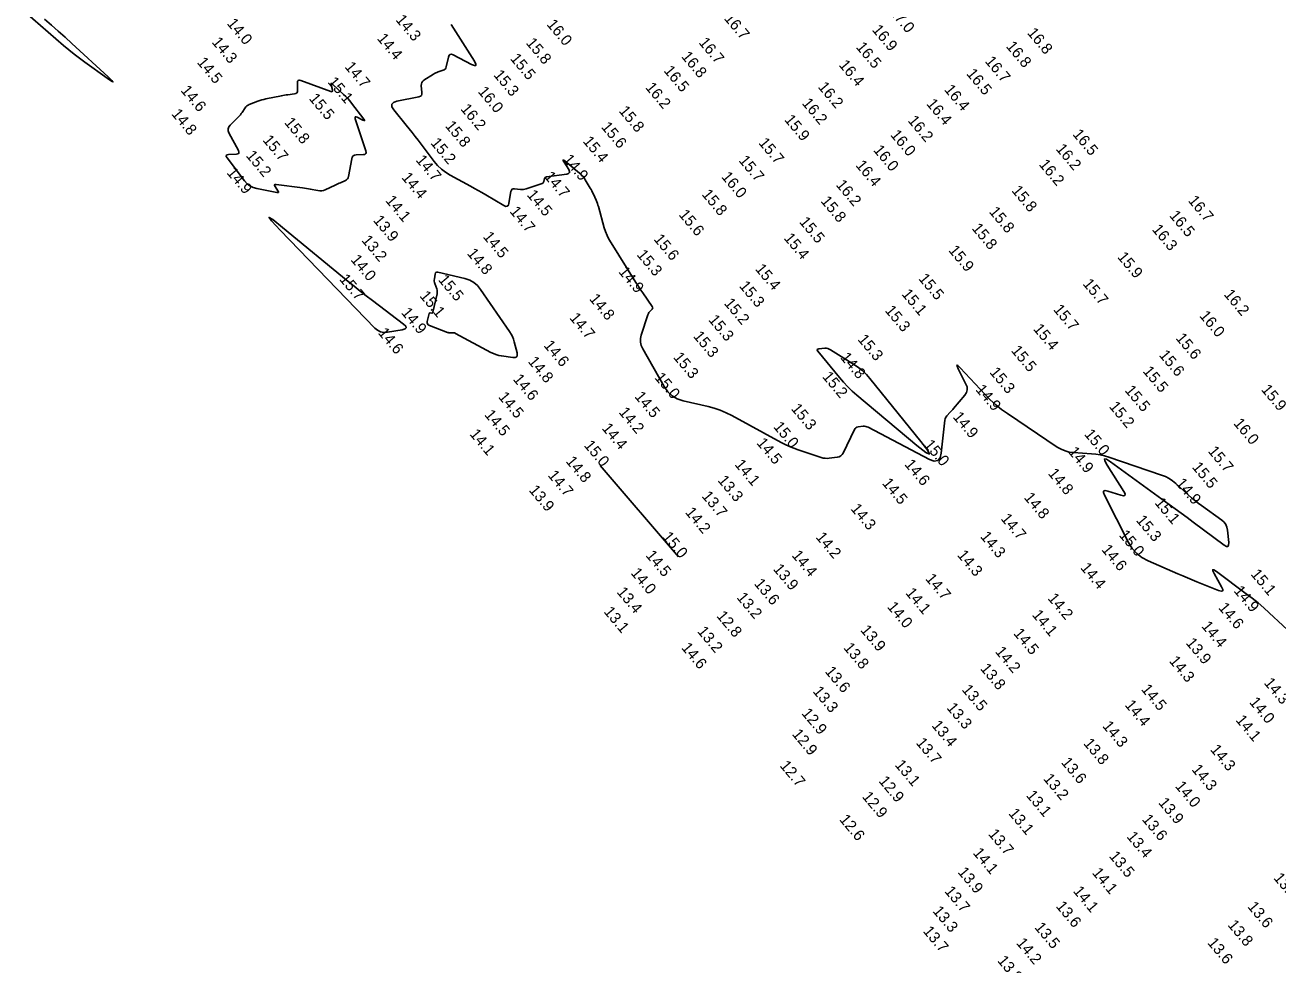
# Model space of a CAD drawing. Extents: x 988130 to 1132882, y 654656 to 841453.
# Drawn here: x 1108628 to 1109193, y 682335 to 682759 of the extents above; entities that cross this region are included whole.
import ezdxf

# ---------------------------------------------------------------- set-up
doc = ezdxf.new("R2010")
doc.units = 0
doc.layers.add('V-TOPO-MAJR', color=7, linetype='Continuous')
doc.layers.add('V-TOPO-SOUN', color=7, linetype='Continuous')

msp = doc.modelspace()

# ---------------------------------------------------------------- linework, layer by layer
at = {"layer": 'V-TOPO-MAJR'}
for points in [[(1108636.86, 682761.26), (1108639.95, 682758.56), (1108643.01, 682755.85), (1108646.06, 682753.11), (1108649.08, 682750.35), (1108665.52, 682735.22), (1108667.2, 682733.62), (1108667.67, 682732.99), (1108666.96, 682733.33), (1108665.05, 682734.64), (1108655.04, 682741.83), (1108652.56, 682743.66), (1108650.12, 682745.54), (1108647.72, 682747.47), (1108645.37, 682749.45), (1108628.06, 682764.38)], [(1109207.17, 682476.66), (1109188.74, 682493.75), (1109186.24, 682496.01), (1109183.68, 682498.2), (1109181.06, 682500.32), (1109178.38, 682502.36), (1109164.89, 682512.38), (1109163.79, 682513.09), (1109163.25, 682513.17), (1109163.27, 682512.63), (1109163.85, 682511.45), (1109167.26, 682505.51), (1109167.8, 682504.29), (1109167.74, 682503.61), (1109167.07, 682503.45), (1109165.79, 682503.83), (1109156.11, 682507.76), (1109153.98, 682508.64), (1109151.84, 682509.53), (1109149.71, 682510.43), (1109147.59, 682511.34), (1109134.13, 682517.14), (1109131.37, 682518.62), (1109128.98, 682520.48), (1109126.96, 682522.75), (1109125.31, 682525.41), (1109114.42, 682546.76), (1109113.99, 682547.91), (1109114.1, 682548.6), (1109114.76, 682548.82), (1109115.97, 682548.58), (1109121.88, 682546.69), (1109123.07, 682546.45), (1109123.69, 682546.64), (1109123.72, 682547.29), (1109123.18, 682548.38), (1109115.65, 682560.32), (1109114.59, 682562.24), (1109114.51, 682563.12), (1109115.38, 682562.98), (1109117.23, 682561.8), (1109143.61, 682542.62), (1109146.33, 682540.63), (1109149.05, 682538.64), (1109151.76, 682536.64), (1109154.47, 682534.63), (1109168.44, 682524.26), (1109169.42, 682523.69), (1109170.08, 682523.69), (1109170.42, 682524.26), (1109170.44, 682525.39), (1109169.89, 682531.03), (1109169.62, 682532.37), (1109169.11, 682533.56), (1109168.33, 682534.6), (1109167.31, 682535.5), (1109158.14, 682542.04), (1109156.61, 682543.17), (1109155.11, 682544.35), (1109153.65, 682545.57), (1109152.23, 682546.84), (1109146.61, 682551.99), (1109145.16, 682553.2), (1109143.6, 682554.23), (1109141.95, 682555.1), (1109140.19, 682555.8), (1109116.39, 682563.89), (1109114.47, 682564.47), (1109112.53, 682564.92), (1109110.56, 682565.24), (1109108.56, 682565.44), (1109100.53, 682565.95), (1109098.57, 682566.2), (1109096.68, 682566.7), (1109094.89, 682567.45), (1109093.17, 682568.45), (1109070.77, 682583.49), (1109068.06, 682585.43), (1109065.47, 682587.51), (1109063, 682589.74), (1109060.66, 682592.11), (1109049.39, 682604.2), (1109048.43, 682605.14), (1109047.98, 682605.36), (1109048.03, 682604.86), (1109048.58, 682603.64), (1109052.06, 682596.85), (1109052.53, 682595.54), (1109052.6, 682594.27), (1109052.25, 682593.05), (1109051.5, 682591.87), (1109046.44, 682585.81), (1109046.08, 682585.38), (1109045.72, 682584.96), (1109045.34, 682584.55), (1109044.96, 682584.14), (1109043.43, 682582.51), (1109043.09, 682582.08), (1109042.83, 682581.62), (1109042.65, 682581.12), (1109042.55, 682580.58), (1109040.93, 682565.73), (1109040.38, 682563.56), (1109039.31, 682562.36), (1109037.72, 682562.14), (1109035.61, 682562.89), (1109007.94, 682577.39), (1109007.42, 682577.62), (1109006.88, 682577.76), (1109006.32, 682577.82), (1109005.75, 682577.8), (1109003.42, 682577.53), (1109002.88, 682577.4), (1109002.42, 682577.16), (1109002.05, 682576.81), (1109001.75, 682576.34), (1108996.67, 682565.75), (1108996.2, 682565.01), (1108995.61, 682564.45), (1108994.88, 682564.06), (1108994.03, 682563.85), (1108990.37, 682563.39), (1108989.45, 682563.32), (1108988.55, 682563.36), (1108987.66, 682563.5), (1108986.78, 682563.74), (1108976.5, 682567.19), (1108974.51, 682567.9), (1108972.56, 682568.7), (1108970.65, 682569.58), (1108968.77, 682570.55), (1108946.57, 682582.6), (1108943.99, 682583.88), (1108941.35, 682584.99), (1108938.64, 682585.92), (1108935.86, 682586.68), (1108924.61, 682589.33), (1108921.97, 682590.22), (1108919.68, 682591.57), (1108917.73, 682593.39), (1108916.12, 682595.67), (1108906.4, 682612.65), (1108905.72, 682614.16), (1108905.38, 682615.71), (1108905.39, 682617.29), (1108905.74, 682618.91), (1108908.64, 682627.97), (1108908.79, 682628.35), (1108908.97, 682628.7), (1108909.19, 682629.04), (1108909.45, 682629.34), (1108910.57, 682630.54), (1108910.79, 682630.84), (1108910.88, 682631.15), (1108910.84, 682631.47), (1108910.67, 682631.8), (1108906.37, 682638.01), (1108905.58, 682639.16), (1108904.81, 682640.32), (1108904.05, 682641.49), (1108903.3, 682642.67), (1108892.12, 682660.46), (1108891.17, 682662.09), (1108890.35, 682663.77), (1108889.65, 682665.52), (1108889.08, 682667.31), (1108886.42, 682676.78), (1108886.2, 682677.51), (1108885.95, 682678.24), (1108885.68, 682678.95), (1108885.38, 682679.66), (1108884.14, 682682.46), (1108883.82, 682683.15), (1108883.48, 682683.84), (1108883.12, 682684.51), (1108882.73, 682685.18), (1108880.49, 682688.94), (1108879.95, 682689.76), (1108879.35, 682690.52), (1108878.68, 682691.23), (1108877.95, 682691.88), (1108871.41, 682697.24), (1108870.8, 682697.69), (1108870.52, 682697.78), (1108870.57, 682697.49), (1108870.95, 682696.83), (1108873.11, 682693.46), (1108873.46, 682692.7), (1108873.43, 682692.12), (1108873.01, 682691.72), (1108872.21, 682691.49), (1108863.05, 682690.22), (1108862.73, 682690.13), (1108862.48, 682689.97), (1108862.3, 682689.74), (1108862.19, 682689.43), (1108861.87, 682688.06), (1108861.75, 682687.75), (1108861.58, 682687.49), (1108861.34, 682687.3), (1108861.04, 682687.16), (1108853.93, 682684.85), (1108853.28, 682684.68), (1108852.63, 682684.57), (1108851.96, 682684.54), (1108851.29, 682684.57), (1108848.6, 682684.85), (1108848, 682684.83), (1108847.53, 682684.62), (1108847.21, 682684.23), (1108847.03, 682683.66), (1108846.12, 682678.33), (1108845.84, 682677.43), (1108845.36, 682676.95), (1108844.68, 682676.89), (1108843.81, 682677.26), (1108835.65, 682682.11), (1108833.96, 682683.1), (1108832.27, 682684.08), (1108830.56, 682685.04), (1108828.85, 682685.99), (1108819.59, 682691.05), (1108817.56, 682692.3), (1108815.69, 682693.74), (1108813.98, 682695.37), (1108812.44, 682697.19), (1108805.16, 682706.75), (1108803.85, 682708.46), (1108802.52, 682710.15), (1108801.19, 682711.83), (1108799.84, 682713.5), (1108794.17, 682720.45), (1108793.32, 682721.83), (1108793.27, 682722.92), (1108794.01, 682723.74), (1108795.53, 682724.27), (1108805.51, 682726.32), (1108806.18, 682726.55), (1108806.64, 682726.95), (1108806.88, 682727.5), (1108806.92, 682728.21), (1108806.62, 682731.36), (1108806.64, 682732.1), (1108806.84, 682732.76), (1108807.23, 682733.32), (1108807.8, 682733.79), (1108812.08, 682736.52), (1108812.59, 682736.82), (1108813.11, 682737.09), (1108813.65, 682737.32), (1108814.2, 682737.52), (1108816.44, 682738.26), (1108816.95, 682738.49), (1108817.35, 682738.82), (1108817.65, 682739.25), (1108817.84, 682739.78), (1108818.9, 682744.23), (1108819.2, 682744.99), (1108819.65, 682745.4), (1108820.27, 682745.48), (1108821.04, 682745.2), (1108829.21, 682740.91), (1108830.53, 682740.35), (1108831.18, 682740.4), (1108831.18, 682741.06), (1108830.52, 682742.33), (1108820.02, 682758.95)], [(1108887.15, 682560.14), (1108922.47, 682518.91)]]:
    msp.add_lwpolyline(points, dxfattribs=at)
for points in [[(1108766.52, 682728.67), (1108766.23, 682728.58), (1108765.78, 682728.69), (1108752.26, 682733.65), (1108751.59, 682733.8), (1108751.13, 682733.67), (1108750.86, 682733.27), (1108750.78, 682732.59), (1108750.88, 682729.23), (1108750.8, 682728.57), (1108750.54, 682728.07), (1108750.09, 682727.74), (1108749.44, 682727.57), (1108746.48, 682727.23), (1108745.74, 682727.13), (1108745.01, 682727.02), (1108744.28, 682726.9), (1108743.55, 682726.76), (1108736.49, 682725.33), (1108735.61, 682725.13), (1108734.73, 682724.9), (1108733.87, 682724.62), (1108733.01, 682724.31), (1108729.09, 682722.8), (1108728.53, 682722.53), (1108728.04, 682722.2), (1108727.6, 682721.79), (1108727.22, 682721.3), (1108725.82, 682719.22), (1108725.46, 682718.71), (1108725.07, 682718.22), (1108724.67, 682717.74), (1108724.23, 682717.29), (1108720.45, 682713.52), (1108719.83, 682712.72), (1108719.54, 682711.87), (1108719.58, 682710.98), (1108719.93, 682710.03), (1108724.21, 682702.07), (1108724.46, 682701.39), (1108724.4, 682700.89), (1108724, 682700.57), (1108723.29, 682700.43), (1108719.79, 682700.24), (1108719.09, 682700.11), (1108718.75, 682699.82), (1108718.75, 682699.36), (1108719.1, 682698.74), (1108726.96, 682688.36), (1108728.09, 682687.11), (1108729.38, 682686.12), (1108730.84, 682685.39), (1108732.47, 682684.93), (1108741.52, 682683.15), (1108741.99, 682683.11), (1108742.24, 682683.23), (1108742.25, 682683.5), (1108742.03, 682683.92), (1108740.71, 682685.92), (1108740.49, 682686.35), (1108740.51, 682686.63), (1108740.75, 682686.78), (1108741.23, 682686.77), (1108753.13, 682685.29), (1108754, 682685.18), (1108754.87, 682685.04), (1108755.73, 682684.89), (1108756.6, 682684.72), (1108760.04, 682684.01), (1108760.89, 682683.9), (1108761.73, 682683.93), (1108762.55, 682684.1), (1108763.35, 682684.4), (1108767.87, 682686.54), (1108768.43, 682686.8), (1108769, 682687.06), (1108769.57, 682687.32), (1108770.14, 682687.57), (1108772.43, 682688.58), (1108772.95, 682688.88), (1108773.34, 682689.27), (1108773.63, 682689.75), (1108773.8, 682690.32), (1108775.25, 682698.4), (1108775.49, 682699.12), (1108775.89, 682699.64), (1108776.47, 682699.97), (1108777.21, 682700.1), (1108780.54, 682700.23), (1108781.24, 682700.35), (1108781.66, 682700.67), (1108781.81, 682701.17), (1108781.69, 682701.87), (1108776.88, 682716.37), (1108776.76, 682716.93), (1108776.86, 682717.24), (1108777.18, 682717.29), (1108777.72, 682717.08), (1108780.3, 682715.76), (1108780.82, 682715.54), (1108781.05, 682715.55), (1108781.02, 682715.79), (1108780.72, 682716.25), (1108775.21, 682723.48), (1108774.38, 682724.52), (1108773.5, 682725.52), (1108772.58, 682726.48), (1108771.61, 682727.39), (1108766.54, 682731.99), (1108766.19, 682732.26), (1108765.97, 682732.29), (1108765.9, 682732.09), (1108765.98, 682731.64), (1108766.57, 682729.41), (1108766.63, 682728.94)], [(1108788.27, 682620.4), (1108789.75, 682620.11), (1108791.35, 682620.2), (1108798.01, 682621.29), (1108799.3, 682621.66), (1108799.83, 682622.21), (1108799.62, 682622.94), (1108798.65, 682623.87), (1108784.6, 682634.45), (1108781.82, 682636.57), (1108779.07, 682638.72), (1108776.34, 682640.89), (1108773.63, 682643.1), (1108744.14, 682667.43), (1108739.71, 682670.95), (1108738.04, 682671.92), (1108739.13, 682670.33), (1108742.99, 682666.19), (1108785.67, 682622.08), (1108786.91, 682621.05)], [(1108812.46, 682643.15), (1108812.55, 682642.62), (1108812.71, 682642.1), (1108813.56, 682639.76), (1108813.72, 682639.2), (1108813.8, 682638.63), (1108813.8, 682638.05), (1108813.71, 682637.47), (1108811.82, 682629.16), (1108811.77, 682629.01), (1108811.67, 682628.91), (1108811.54, 682628.85), (1108811.38, 682628.85), (1108810.66, 682628.93), (1108810.49, 682628.93), (1108810.36, 682628.88), (1108810.27, 682628.77), (1108810.21, 682628.62), (1108809.3, 682625.03), (1108809.24, 682624.43), (1108809.37, 682623.93), (1108809.71, 682623.53), (1108810.24, 682623.24), (1108818.44, 682620.13), (1108818.74, 682620.03), (1108819.04, 682619.96), (1108819.34, 682619.93), (1108819.65, 682619.92), (1108820.9, 682619.96), (1108821.21, 682619.95), (1108821.51, 682619.9), (1108821.8, 682619.82), (1108822.08, 682619.69), (1108837.94, 682611.1), (1108839.08, 682610.54), (1108840.27, 682610.09), (1108841.49, 682609.75), (1108842.74, 682609.52), (1108847.85, 682608.8), (1108848.92, 682608.8), (1108849.59, 682609.15), (1108849.87, 682609.86), (1108849.76, 682610.92), (1108848.51, 682615.87), (1108848.14, 682617.08), (1108847.67, 682618.25), (1108847.11, 682619.37), (1108846.43, 682620.45), (1108833.33, 682639.5), (1108831.92, 682641.21), (1108830.28, 682642.59), (1108828.41, 682643.63), (1108826.3, 682644.33), (1108814.06, 682647.26), (1108813.58, 682647.31), (1108813.21, 682647.18), (1108812.96, 682646.89), (1108812.82, 682646.43), (1108812.49, 682644.23), (1108812.44, 682643.69)], [(1108984.99, 682612.4), (1108985.25, 682612.63), (1108985.8, 682612.74), (1108988.51, 682612.95), (1108989.18, 682612.95), (1108989.82, 682612.84), (1108990.44, 682612.63), (1108991.03, 682612.32), (1109001.82, 682605.51), (1109003.75, 682604.19), (1109005.55, 682602.72), (1109007.23, 682601.1), (1109008.77, 682599.34), (1109031.77, 682570.99), (1109034.87, 682566.91), (1109035.6, 682565.24), (1109033.94, 682566), (1109029.92, 682569.17), (1109002.88, 682591.85), (1109000.79, 682593.68), (1108998.79, 682595.61), (1108996.88, 682597.63), (1108995.07, 682599.73), (1108985.3, 682611.58), (1108985.01, 682612.05)]]:
    msp.add_lwpolyline(points, close=True, dxfattribs=at)

# ---------------------------------------------------------------- texts
at = {"layer": 'V-TOPO-SOUN'}
for s, p in [('16.7 ', (1108942.8, 682761.5)), ('17.0 ', (1109017.2, 682764.6)), ('14.0 ', (1108718.76, 682759.24)), ('14.3 ', (1108794.79, 682760.9)), ('16.0 ', (1108862.87, 682758.81)), ('16.9 ', (1109009.48, 682756.37)), ('14.3 ', (1108711.96, 682750.83)), ('14.4 ', (1108786.42, 682752.46)), ('15.8 ', (1108853.53, 682750.45)), ('16.7 ', (1108931.38, 682750.62)), ('16.8 ', (1109079.39, 682754.98)), ('16.8 ', (1108923.55, 682744.33)), ('16.5 ', (1109002.22, 682748.59)), ('16.8 ', (1109069.84, 682748.94)), ('14.5 ', (1108705.28, 682741.73)), ('14.7 ', (1108771.85, 682739.69)), ('15.5 ', (1108846.4, 682743.41)), ('16.4 ', (1108994.52, 682740.51)), ('16.7 ', (1109060.36, 682742.19)), ('15.3 ', (1108838.91, 682736.03)), ('16.5 ', (1108915.6, 682737.96)), ('16.5 ', (1109051.99, 682736.58)), ('14.6 ', (1108697.96, 682729.05)), ('15.1 ', (1108764.17, 682732.83)), ('16.0 ', (1108831.88, 682728.52)), ('16.2 ', (1108907.33, 682730.38)), ('16.2 ', (1108985.11, 682730.62)), ('16.4 ', (1109042, 682729.4)), ('15.5 ', (1108755.75, 682725.4)), ('16.2 ', (1108977.88, 682723.29)), ('16.4 ', (1109033.97, 682723.01)), ('14.8 ', (1108693.76, 682718.48)), ('16.2 ', (1108824.07, 682720.71)), ('15.8 ', (1108895.38, 682719.81)), ('15.8 ', (1108744.64, 682714.57)), ('15.8 ', (1108817.09, 682713.06)), ('15.6 ', (1108887.42, 682712.58)), ('15.9 ', (1108969.96, 682715.85)), ('16.2 ', (1109025.6, 682715.45)), ('15.7 ', (1108734.9, 682706.66)), ('15.2 ', (1108810.52, 682705.39)), ('15.4 ', (1108879.17, 682706.13)), ('15.7 ', (1108958.33, 682705.42)), ('16.0 ', (1109017.74, 682709.02)), ('16.5 ', (1109099.86, 682709.31)), ('15.2 ', (1108727.33, 682699.68)), ('16.0 ', (1109010.03, 682702.18)), ('16.2 ', (1109092.3, 682702.7)), ('14.7 ', (1108803.88, 682697.66)), ('14.9 ', (1108870.18, 682697.93)), ('15.7 ', (1108949.4, 682697.46)), ('16.4 ', (1109002.08, 682695.33)), ('16.2 ', (1109084.68, 682695.71)), ('14.9 ', (1108718.67, 682691.96)), ('14.4 ', (1108797.46, 682689.82)), ('14.7 ', (1108861.74, 682690.22)), ('16.0 ', (1108941.59, 682690.12)), ('15.8 ', (1108932.76, 682682.2)), ('16.2 ', (1108993.19, 682686.51)), ('15.8 ', (1109072.38, 682683.9)), ('14.1 ', (1108790.19, 682679.42)), ('14.5 ', (1108853.92, 682681.98)), ('15.8 ', (1108986.35, 682679.17)), ('16.7 ', (1109151.89, 682679.39)), ('14.7 ', (1108846.18, 682674.54)), ('15.6 ', (1108922.37, 682673.06)), ('15.8 ', (1109062.2, 682674.37)), ('16.5 ', (1109143.45, 682672.64)), ('13.9 ', (1108784.68, 682670.49)), ('15.5 ', (1108976.67, 682669.8)), ('15.8 ', (1109054.43, 682666.9)), ('16.3 ', (1109135.63, 682666.4)), ('13.2 ', (1108779.45, 682661.5)), ('14.5 ', (1108834.14, 682663.12)), ('15.6 ', (1108911.06, 682662.02)), ('15.4 ', (1108969.72, 682662.49)), ('14.8 ', (1108826.95, 682655.6)), ('15.3 ', (1108903.47, 682654.99)), ('15.9 ', (1109043.94, 682656.96)), ('15.9 ', (1109120.02, 682653.99)), ('14.0 ', (1108774.54, 682652.76)), ('15.4 ', (1108956.8, 682648.59)), ('15.7 ', (1108769.41, 682643.98)), ('15.5 ', (1108813.98, 682643.71)), ('14.9 ', (1108895.22, 682647.33)), ('15.5 ', (1109030.41, 682644.23)), ('15.3 ', (1108949.6, 682640.9)), ('15.1 ', (1109022.8, 682637.27)), ('15.7 ', (1109104.44, 682641.89)), ('16.2 ', (1109168.01, 682637.11)), ('15.1 ', (1108805.62, 682636.43)), ('14.8 ', (1108882.05, 682635.11)), ('15.2 ', (1108942.77, 682633.12)), ('14.9 ', (1108797.33, 682628.89)), ('14.7 ', (1108873.14, 682626.56)), ('15.3 ', (1108935.75, 682625.66)), ('15.3 ', (1109015.27, 682629.87)), ('15.7 ', (1109091.15, 682630.3)), ('16.0 ', (1109156.99, 682627.47)), ('15.4 ', (1109082.09, 682621.57)), ('14.6 ', (1108786.87, 682619.8)), ('15.3 ', (1108928.88, 682618.29)), ('15.3 ', (1109003.03, 682616.82)), ('15.6 ', (1109146.31, 682617.4)), ('14.6 ', (1108861.5, 682614.14)), ('15.3 ', (1108919.91, 682608.77)), ('14.8 ', (1108995.16, 682608.69)), ('15.5 ', (1109072.14, 682611.81)), ('15.6 ', (1109138.77, 682609.78)), ('14.8 ', (1108854.44, 682606.85)), ('14.6 ', (1108847.67, 682598.9)), ('15.0 ', (1108911.49, 682599.59)), ('15.2 ', (1108987.06, 682600.05)), ('15.3 ', (1109062.45, 682602.03)), ('15.5 ', (1109131.48, 682602.51)), ('14.9 ', (1109056.14, 682594.2)), ('15.5 ', (1109123.36, 682593.86)), ('15.9 ', (1109184.81, 682594.23)), ('14.5 ', (1108841.06, 682590.91)), ('14.5 ', (1108902.47, 682591.08)), ('15.2 ', (1109116.29, 682586.57)), ('14.5 ', (1108834.82, 682582.87)), ('14.2 ', (1108895.33, 682584.01)), ('15.3 ', (1108972.98, 682585.62)), ('14.9 ', (1109045.88, 682581.9)), ('14.4 ', (1108887.71, 682576.8)), ('15.0 ', (1108964.99, 682577.47)), ('16.0 ', (1109172.34, 682579)), ('14.1 ', (1108828.13, 682574.18)), ('14.5 ', (1108957.45, 682570.16)), ('15.0 ', (1109032.85, 682569.35)), ('15.0 ', (1109105.08, 682574.12)), ('15.0 ', (1108879.65, 682569.08)), ('14.9 ', (1109097.87, 682566.18)), ('15.7 ', (1109160.84, 682566.47)), ('14.8 ', (1108871.47, 682561.9)), ('14.1 ', (1108947.57, 682560.45)), ('14.6 ', (1109024.1, 682560.51)), ('15.5 ', (1109153.67, 682559.29)), ('14.7 ', (1108863.39, 682555.57)), ('13.3 ', (1108939.95, 682553.28)), ('14.8 ', (1109088.77, 682556.42)), ('13.9 ', (1108854.84, 682548.88)), ('14.5 ', (1109014.01, 682552.04)), ('14.9 ', (1109146.31, 682551.98)), ('13.7 ', (1108932.75, 682546.2)), ('14.8 ', (1109077.93, 682545.55)), ('15.1 ', (1109136.81, 682543.2)), ('14.2 ', (1108925.27, 682538.91)), ('14.3 ', (1108999.82, 682540.54)), ('14.7 ', (1109067.48, 682536.07)), ('15.3 ', (1109128.44, 682535.33)), ('15.0 ', (1108914.97, 682527.85)), ('14.2 ', (1108984.11, 682527.71)), ('14.3 ', (1109058.22, 682528)), ('15.0 ', (1109120.73, 682528.63)), ('14.5 ', (1108907.49, 682519.49)), ('14.4 ', (1108973.29, 682519.51)), ('14.3 ', (1109047.85, 682519.63)), ('14.6 ', (1109112.87, 682522.11)), ('13.9 ', (1108964.88, 682513.36)), ('14.4 ', (1109103.39, 682513.92)), ('14.0 ', (1108900.75, 682511.57)), ('14.7 ', (1109033.5, 682508.99)), ('15.1 ', (1109180.12, 682511.03)), ('13.4 ', (1108894.45, 682502.96)), ('13.6 ', (1108956.34, 682506.74)), ('14.1 ', (1109024.53, 682502.59)), ('14.9 ', (1109172.47, 682503.53)), ('13.2 ', (1108948.48, 682500.5)), ('14.0 ', (1109016.29, 682496.32)), ('14.2 ', (1109088.62, 682500.16)), ('14.6 ', (1109165.52, 682495.93)), ('13.1 ', (1108888.59, 682494.12)), ('12.8 ', (1108939.4, 682492.2)), ('14.1 ', (1109081.59, 682492.69)), ('13.2 ', (1108930.73, 682485.24)), ('13.9 ', (1109004.23, 682485.83)), ('14.4 ', (1109157.91, 682487.59)), ('14.5 ', (1109073.2, 682484.33)), ('13.9 ', (1109150.88, 682480.03)), ('14.6 ', (1108923.55, 682477.89)), ('13.8 ', (1108996.62, 682477.86)), ('14.2 ', (1109064.93, 682476.14)), ('13.8 ', (1109058.22, 682468.5)), ('14.3 ', (1109143.35, 682471.89)), ('13.6 ', (1108988.24, 682467.19)), ('14.3 ', (1109186.06, 682462.04)), ('13.3 ', (1108982.77, 682458.22)), ('13.5 ', (1109049.95, 682458.97)), ('14.5 ', (1109130.73, 682459.16)), ('13.3 ', (1109043.08, 682450.8)), ('14.4 ', (1109123.38, 682452.06)), ('14.0 ', (1109179.46, 682453.33)), ('12.9 ', (1108977.71, 682448.33)), ('14.1 ', (1109173.33, 682445.28)), ('13.4 ', (1109036.33, 682442.84)), ('14.3 ', (1109113.28, 682442.6)), ('12.9 ', (1108973.43, 682438.95)), ('13.7 ', (1109029.27, 682435.02)), ('13.8 ', (1109104.74, 682434.75)), ('14.3 ', (1109161.86, 682431.98)), ('12.7 ', (1108967.92, 682424.7)), ('13.1 ', (1109019.76, 682425.06)), ('13.6 ', (1109094.7, 682426.18)), ('14.3 ', (1109153.49, 682423.02)), ('12.9 ', (1109012.48, 682417.79)), ('13.2 ', (1109086.65, 682418.84)), ('13.1 ', (1109078.93, 682411.31)), ('14.0 ', (1109146.05, 682415.48)), ('12.9 ', (1109005.01, 682410.74)), ('13.9 ', (1109138.51, 682408.02)), ('12.6 ', (1108994.74, 682400.46)), ('13.1 ', (1109070.97, 682403.19)), ('13.6 ', (1109131.1, 682400.51)), ('13.7 ', (1109061.85, 682393.91)), ('13.4 ', (1109124.22, 682392.74)), ('14.1 ', (1109054.92, 682385.42)), ('13.5 ', (1109116.29, 682383.93)), ('13.9 ', (1109048.11, 682376.73)), ('14.1 ', (1109108.65, 682376.45)), ('13.5 ', (1109190.4, 682374.12)), ('13.7 ', (1109042.12, 682368.13)), ('14.1 ', (1109100.08, 682368.19)), ('13.6 ', (1109092.31, 682361.38)), ('13.6 ', (1109178.69, 682361.17)), ('13.3 ', (1109036.78, 682359.2)), ('13.7 ', (1109032.44, 682350.13)), ('13.5 ', (1109082.69, 682351.83)), ('13.8 ', (1109169.73, 682352.93)), ('14.2 ', (1109074.47, 682344.8)), ('13.6 ', (1109160.62, 682344.88)), ('13.8 ', (1109065.96, 682336.82))]:
    msp.add_text(s, height=5, rotation=310, dxfattribs=at).set_placement(p)

doc.saveas('drawing.dxf')
